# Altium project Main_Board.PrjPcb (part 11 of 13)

## Sheet eMMC.SchDoc: Pamięć nieulotna  eMMC
size A3; Organization: Altium Limited; Address1: L3, 12a Rodborough Rd; Address2: Frenchs Forest; Address3: NSW; Address4: Australia 2086
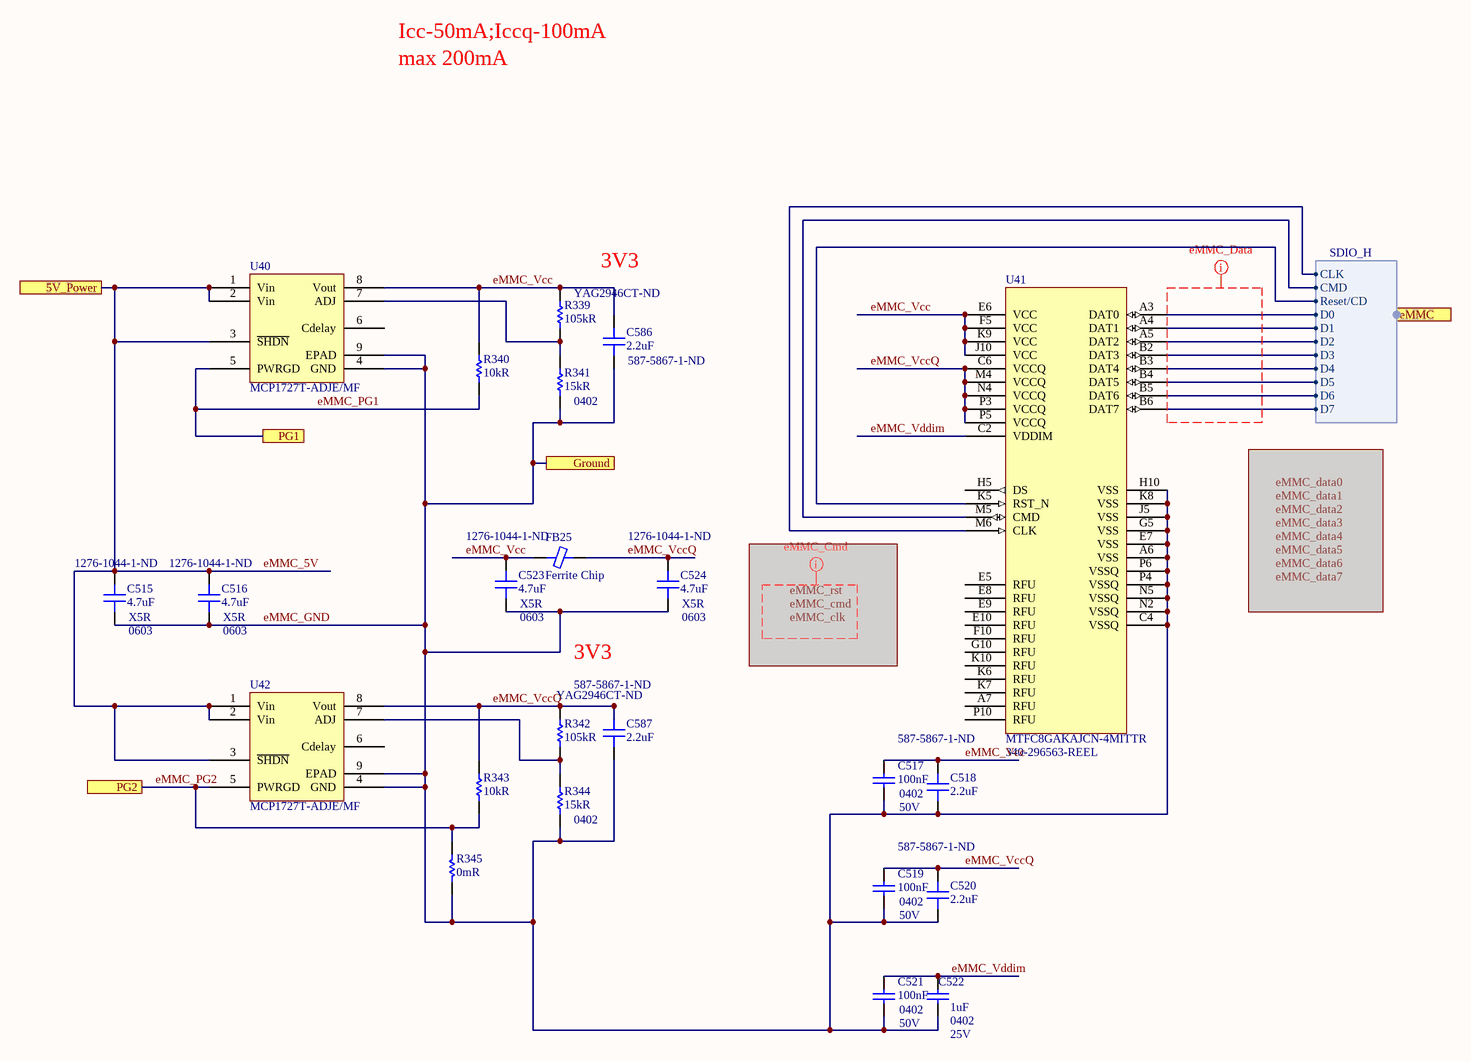
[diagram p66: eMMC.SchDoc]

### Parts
C515  4.7uF  Supplier Part Number 1: 1276-1044-1-ND  Case/Package: 0603  Dielectric: X5R  [CAP 0603/1608 RF]
C516  4.7uF  Supplier Part Number 1: 1276-1044-1-ND  Case/Package: 0603  Dielectric: X5R  [CAP 0603/1608 RF]
C517  100nF  Case Code (Imperial): 0402  Voltage: 50V  [CAP 0402/1005 KK]
C518  2.2uF  Supplier Part Number 1: 587-5867-1-ND  [CAP 0402/1005 KK]
C519  100nF  Case Code (Imperial): 0402  Voltage: 50V  [CAP 0402/1005 KK]
C520  2.2uF  Supplier Part Number 1: 587-5867-1-ND  [CAP 0402/1005 KK]
C521  100nF  Case Code (Imperial): 0402  Voltage: 50V  [CAP 0402/1005 KK]
C522  1uF  Case/Package: 0402  Voltage Rating: 25V  [CAP 0402/1005 KK]
C523  4.7uF  Supplier Part Number 1: 1276-1044-1-ND  Case/Package: 0603  Dielectric: X5R  [CAP 0603/1608 RF]
C524  4.7uF  Supplier Part Number 1: 1276-1044-1-ND  Case/Package: 0603  Dielectric: X5R  [CAP 0603/1608 RF]
C586  2.2uF  Supplier Part Number 1: 587-5867-1-ND  [CAP 0402/1005 KK]
C587  2.2uF  Supplier Part Number 1: 587-5867-1-ND  [CAP 0402/1005 KK]
FB25  Ferrite Chip  [FER 0603/1608]
R339  105kR  Supplier Part Number 1: YAG2946CT-ND  [RES 0402/1005 RF KK]
R340  10kR  [RES 0402/1005 RF KK]
R341  15kR  Case Code (Imperial): 0402  [RES 0402/1005 RF KK]
R342  105kR  Supplier Part Number 1: YAG2946CT-ND  [RES 0402/1005 RF KK]
R343  10kR  [RES 0402/1005 RF KK]
R344  15kR  Case Code (Imperial): 0402  [RES 0402/1005 RF KK]
R345  0mR  [RES 0402/1005 RF KK]
U40  MCP1727T-ADJE/MF  [MCP1727T-ADJE/MF]
U41  MTFC8GAKAJCN-4MITTR  Supplier Part Number 1: 340-296563-REEL  [MTFC8GAKAJCN-4M IT TR]
U42  MCP1727T-ADJE/MF  [MCP1727T-ADJE/MF]

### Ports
5V_Power, eMMC (harness SDIO_H), Ground, PG1, PG2

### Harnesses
SDIO_H: CLK, CMD, Reset/CD, D0, D1, D2, D3, D4, D5, D6, D7

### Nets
eMMC_GND: C515.1 C516.1 C517.1 C518.1 C519.1 C520.1 C521.1 C522.2 C523.1 C524.1 C586.1 C587.1 R341.1 R344.1 R345.2 U40.4(GND) U40.9(EPAD) U41.A6(VSS) U41.C4(VSSQ) U41.E7(VSS) U41.G5(VSS) U41.H10(VSS) U41.J5(VSS) U41.K8(VSS) U41.N2(VSSQ) U41.N5(VSSQ) U41.P4(VSSQ) U41.P6(VSSQ) U42.4(GND) U42.9(EPAD) ; port Ground  [project net B503_Ground]
eMMC_5V: C515.2 C516.2 U40.1(Vin) U40.2(Vin) U40.3(~{SHDN}) U42.1(Vin) U42.2(Vin) U42.3(~{SHDN}) ; port 5V_Power  [project net 5V_RAIL]
eMMC_clk: U41.M6(CLK) ; port eMMC.CLK
eMMC_cmd: U41.M5(CMD) ; port eMMC.CMD
eMMC_data0: U41.A3(DAT0) ; port eMMC.D0
eMMC_data1: U41.A4(DAT1) ; port eMMC.D1
eMMC_data2: U41.A5(DAT2) ; port eMMC.D2
eMMC_data3: U41.B2(DAT3) ; port eMMC.D3
eMMC_data4: U41.B3(DAT4) ; port eMMC.D4
eMMC_data5: U41.B4(DAT5) ; port eMMC.D5
eMMC_data6: U41.B5(DAT6) ; port eMMC.D6
eMMC_data7: U41.B6(DAT7) ; port eMMC.D7
eMMC_PG1: R340.1 U40.5(PWRGD) ; port PG1
eMMC_PG2: R343.1 R345.1 U42.5(PWRGD) ; port PG2
eMMC_rst: U41.K5(RST_N) ; port eMMC.Reset/CD
eMMC_Vcc: C517.2 C518.2 C523.2 C586.2 FB25.1 R339.2 R340.2 U40.8(Vout) U41.E6(VCC) U41.F5(VCC) U41.J10(VCC) U41.K9(VCC)
eMMC_VccQ: C519.2 C520.2 C524.2 C587.2 FB25.2 R342.2 R343.2 U41.C6(VCCQ) U41.M4(VCCQ) U41.N4(VCCQ) U41.P3(VCCQ) U41.P5(VCCQ) U42.8(Vout)
eMMC_Vddim: C521.2 C522.1 U41.C2(VDDIM)
NetR339_1: R339.1 R341.2 U40.7(ADJ)
NetR342_1: R342.1 R344.2 U42.7(ADJ)

Not connected (* = marked no-connect by the designer): U40 6(Cdelay); U41 A7(RFU) E5(RFU) E8(RFU) E9(RFU) E10(RFU) F10(RFU) G10(RFU) H5(DS) K6(RFU) K7(RFU) K10(RFU) P10(RFU); U42 6(Cdelay)

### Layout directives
net class eMMC_Data: (no net found under the mark)
net class eMMC_Cmd: eMMC_clk, eMMC_cmd, eMMC_rst

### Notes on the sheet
- Icc-50mA;Iccq-100mA
- max 200mA
- 3V3

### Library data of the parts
C515 C516 C523 C524 = Capacitor: Manufacturer: Samsung; Manufacturer Part Number: CL10A475KP8NNNC; Tolerance: 10%; Voltage Rating: 10V
C517 C519 C521 = Capacitor: CAP CER 0.1UF 50V X5R 0402; Manufacturer: Murata; Manufacturer Part Number: GRM155R61H104KE14D; Dielectric Material: Ceramic; Dissipation Factor: 0.025%; Tolerance: 10%
C518 C520 C586 C587 = Capacitor: CAP CER 2.2UF 6.3V X5R 0402; Manufacturer: Taiyo Yuden; Manufacturer Part Number: JMK105BJ225KV-F; Tolerance: 10%
C522 = Capacitor: MURATA - GRT155R61E105KE01D - SMD Multilayer Ceramic Capacitor, 1 µF, 25 V, 0402 [1005 Metric], ± 10%, X5R, GRT Series - SMD Multilayer Ceramic Capacitor, 1 µF, 25 V, 0402 [1005 Metric], ± 10%, X5R, GRT Series
FB25 = Ferrite Chip: SMT Ferrite Chip; Manufacturer: TDK; Manufacturer Part Number: MPZ1608S331ATA00; Tolerance: 25%; Impedance: 330R; DC Resistance (DCR): 80mR; Max DC Current: 1.7A
R339 R342 = Resistor: Thick Film Resistors - SMD 105K OHM 1%; Manufacturer: Yageo; Manufacturer Part Number: RC0402FR-07105KL; Power Rating: 62.5mW; Voltage Rating: 50V; Max Power Dissipation: 63mW; Temperature Coefficient: 100ppm/°C
R340 R343 = Resistor: Manufacturer 1: Yageo; Manufacturer Part Number 1: RC0402FR-0710KL; Tolerance: 1%; Temperature Coefficient: 100ppm/°C; Voltage Rating: 50V; Power Rating: 62.5mW
R341 R344 = Resistor: Manufacturer: Panasonic; Manufacturer Part Number: ERJ-2RKF1502X; Tolerance: 1%; Voltage Rating: 50V; Power Rating: 100mW; Temperature Coefficient: 100ppm/°C
R345 = Resistor: Manufacturer 1: Yageo; Manufacturer Part Number 1: RC0402JR-070RL; Power Rating: 62.5mW; Tolerance: 5%; Voltage Rating: 50V; Max Power Dissipation: 63mW; Temperature Coefficient: 200ppm/°C
U40 U42 = MCP1727T-ADJE/MF: IC REG LDO ADJ 1.5A 8DFN; Manufacturer 1: Microchip; Number of Outputs: 1; Min Input Voltage: 2.3V; Max Input Voltage: 6V; Output Voltage: 5V; Dropout Voltage: 330mV; Input Bias Current: 120uA; Reference Voltage: 410mV; Polarity: Positive; Accuracy: 0.5%; Output Type: Adjustable
U41 = MTFC8GAKAJCN-4MITTR: IC FLASH 64G MMC; Manufacturer 1: Micron Technology

## Sheet GTR.SchDoc: GTR
size A3; Organization: Altium Limited; Address1: L3, 12a Rodborough Rd; Address2: Frenchs Forest; Address3: NSW; Address4: Australia 2086
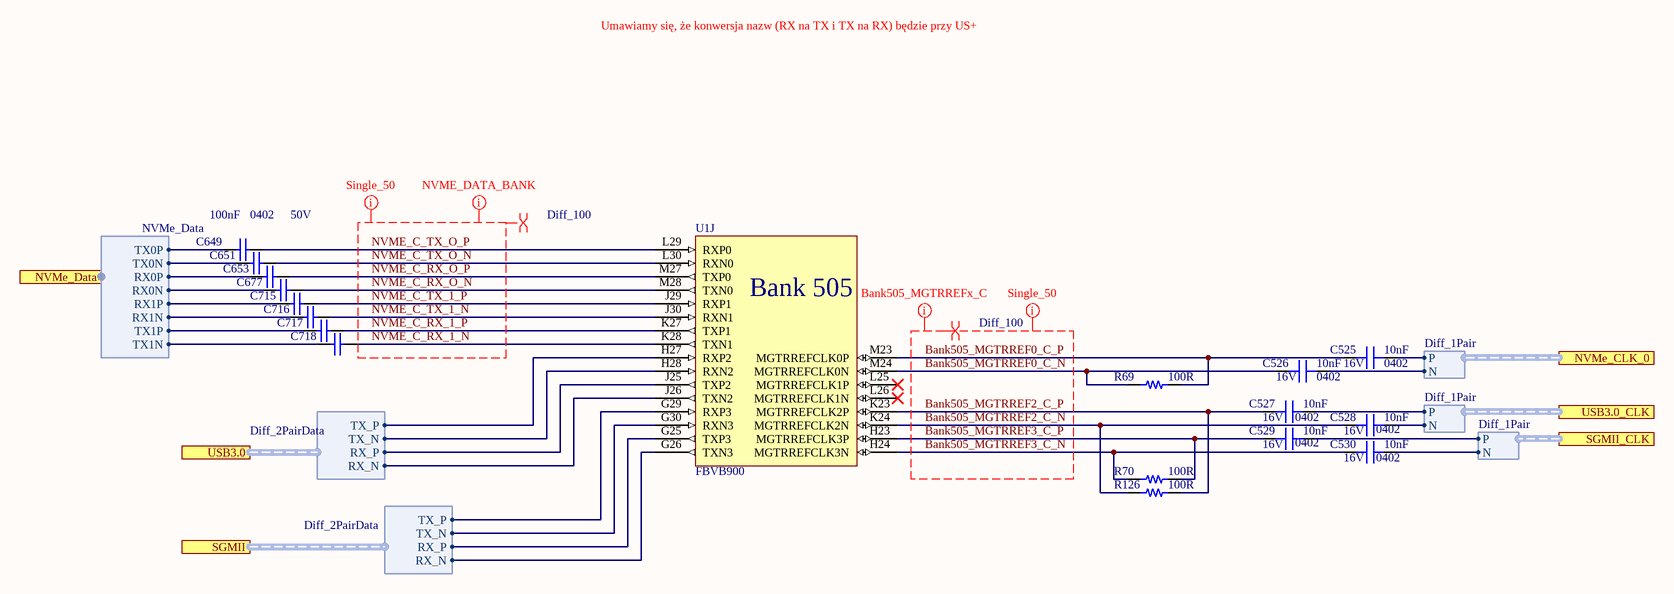
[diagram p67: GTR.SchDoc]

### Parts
C525  10nF  Case/Package: 0402  Voltage Rating (DC): 16V  [CAP 0402/1005 KK]
C526  10nF  Case/Package: 0402  Voltage Rating (DC): 16V  [CAP 0402/1005 KK]
C527  10nF  Case/Package: 0402  Voltage Rating (DC): 16V  [CAP 0402/1005 KK]
C528  10nF  Case/Package: 0402  Voltage Rating (DC): 16V  [CAP 0402/1005 KK]
C529  10nF  Case/Package: 0402  Voltage Rating (DC): 16V  [CAP 0402/1005 KK]
C530  10nF  Case/Package: 0402  Voltage Rating (DC): 16V  [CAP 0402/1005 KK]
C649  100nF  Case Code (Imperial): 0402  Voltage: 50V  [CAP 0402/1005 KK]
C651  100nF  [CAP 0402/1005 KK]  (value not drawn)
C653  100nF  [CAP 0402/1005 KK]  (value not drawn)
C677  100nF  [CAP 0402/1005 KK]  (value not drawn)
C715  100nF  [CAP 0402/1005 KK]  (value not drawn)
C716  100nF  [CAP 0402/1005 KK]  (value not drawn)
C717  100nF  [CAP 0402/1005 KK]  (value not drawn)
C718  100nF  [CAP 0402/1005 KK]  (value not drawn)
R69  100R  [RES 0402/1005 RF KK]
R70  100R  [RES 0402/1005 RF KK]
R126  100R  [RES 0402/1005 RF KK]
U1  FBVB900  [FBVB900 XX]  (part J of 23)

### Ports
NVMe_CLK_0 (harness Diff_1Pair), NVMe_Data (harness NVMe_Data), SGMII (harness Diff_2PairData), SGMII_CLK (harness Diff_1Pair), USB3.0 (harness Diff_2PairData), USB3.0_CLK (harness Diff_1Pair)

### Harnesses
NVMe_Data: RX0P, RX0N, TX0P, TX0N, RX1P, RX1N, TX1P, TX1N
Diff_1Pair: P, N
Diff_2PairData: RX_P, RX_N, TX_P, TX_N

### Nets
Bank505_MGTRREF0_C_N: C526.1 R69.2 U1.M24(MGTRREFCLK0N)
Bank505_MGTRREF0_C_P: C525.1 R69.1 U1.M23(MGTRREFCLK0P)
Bank505_MGTRREF2_C_N: C528.1 R126.2 U1.K24(MGTRREFCLK2N)
Bank505_MGTRREF2_C_P: C527.1 R126.1 U1.K23(MGTRREFCLK2P)
Bank505_MGTRREF3_C_N: C530.1 R70.2 U1.H24(MGTRREFCLK3N)
Bank505_MGTRREF3_C_P: C529.1 R70.1 U1.H23(MGTRREFCLK3P)
LTC6952_0_MATCH_Out7_N: C526.2 ; port NVMe_CLK_0.N
LTC6952_0_MATCH_Out7_P: C525.2 ; port NVMe_CLK_0.P
LTC6952_0_MATCH_Out8_N: C528.2 ; port USB3.0_CLK.N
LTC6952_0_MATCH_Out8_P: C527.2 ; port USB3.0_CLK.P
LTC6952_0_MATCH_Out9_N: C530.2 ; port SGMII_CLK.N
LTC6952_0_MATCH_Out9_P: C529.2 ; port SGMII_CLK.P
NVME_C_RX_1_N: C718.1 U1.K28(TXN1)
NVME_C_RX_1_P: C717.1 U1.K27(TXP1)
NVME_C_RX_O_N: C677.1 U1.M28(TXN0)
NVME_C_RX_O_P: C653.1 U1.M27(TXP0)
NVME_C_TX_1_N: C716.1 U1.J30(RXN1)
NVME_C_TX_1_P: C715.1 U1.J29(RXP1)
NVME_C_TX_O_N: C651.1 U1.L30(RXN0)
NVME_C_TX_O_P: C649.1 U1.L29(RXP0)
NVMe_Rx_0_N: C677.2 ; port NVMe_Data.RX0N
NVMe_Rx_0_P: C653.2 ; port NVMe_Data.RX0P
NVMe_Rx_1_N: C716.2 ; port NVMe_Data.RX1N
NVMe_Rx_1_P: C715.2 ; port NVMe_Data.RX1P
NVMe_Tx_0_N: C651.2 ; port NVMe_Data.TX0N
NVMe_Tx_0_P: C649.2 ; port NVMe_Data.TX0P
NVMe_Tx_1_N: C718.2 ; port NVMe_Data.TX1N
NVMe_Tx_1_P: C717.2 ; port NVMe_Data.TX1P
SGMI_C_Rx_N: U1.G26(TXN3) ; port SGMII.RX_N
SGMI_C_Rx_P: U1.G25(TXP3) ; port SGMII.RX_P
SGMI_C_Tx_N: U1.G29(RXP3) ; port SGMII.TX_P
SGMI_C_Tx_P: U1.G30(RXN3) ; port SGMII.TX_N
USB_RX_N: U1.J25(TXP2) ; port USB3.0.RX_P
USB_RX_P: U1.J26(TXN2) ; port USB3.0.RX_N
USB_TX_N: U1.H28(RXN2) ; port USB3.0.TX_N
USB_TX_P: U1.H27(RXP2) ; port USB3.0.TX_P

Not connected (* = marked no-connect by the designer): U1 L25(MGTRREFCLK1P)* L26(MGTRREFCLK1N)*

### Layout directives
net class Bank505_MGTRREFx_C: Bank505_MGTRREF0_C_N, Bank505_MGTRREF0_C_P, Bank505_MGTRREF2_C_N, Bank505_MGTRREF2_C_P, Bank505_MGTRREF3_C_N, Bank505_MGTRREF3_C_P
net class NVME_DATA_BANK: NVME_C_RX_1_N, NVME_C_RX_1_P, NVME_C_RX_O_N, NVME_C_RX_O_P, NVME_C_TX_1_N, NVME_C_TX_1_P, NVME_C_TX_O_N, NVME_C_TX_O_P
net class Single_50: Bank505_MGTRREF0_C_N, Bank505_MGTRREF0_C_P, Bank505_MGTRREF2_C_N, Bank505_MGTRREF2_C_P, Bank505_MGTRREF3_C_N, Bank505_MGTRREF3_C_P, NVME_C_RX_1_N, NVME_C_RX_1_P, NVME_C_RX_O_N, NVME_C_RX_O_P, NVME_C_TX_1_N, NVME_C_TX_1_P, NVME_C_TX_O_N, NVME_C_TX_O_P
differential pair; differential pair class Diff_100: Bank505_MGTRREF0_C_N, Bank505_MGTRREF0_C_P, Bank505_MGTRREF2_C_N, Bank505_MGTRREF2_C_P, Bank505_MGTRREF3_C_N, Bank505_MGTRREF3_C_P, NVME_C_RX_1_N, NVME_C_RX_1_P, NVME_C_RX_O_N, NVME_C_RX_O_P, NVME_C_TX_1_N, NVME_C_TX_1_P, NVME_C_TX_O_N, NVME_C_TX_O_P

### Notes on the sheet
- Umawiamy się, że konwersja nazw (RX na TX i TX na RX) będzie przy US+

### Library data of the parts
C525-C530 = Capacitor: Manufacturer: KEMET; Manufacturer Part Number: C0402C103K4RACTU; Dielectric Material: Ceramic; Tolerance: 10%; Dielectric: X7R; Dissipation Factor: 3.5%
C649 C651 C653 C677 C715-C718 = Capacitor: as C517 on sheet eMMC
R69 R70 R126 = Resistor: Manufacturer: Vishay Dale; Manufacturer Part Number: CRCW0402100RFKED; Tolerance: 1%; Power Rating: 63mW; Voltage Rating: 50V; Temperature Coefficient: 100ppm/°C
U1 = FBVB900: FPGA Zynq UltraScale+ Family 192150 Cells 20nm Technology 0.85V 900-Pin FCBGA Tray; Manufacturer Part Number: XCZU4CG-1FBVB900E; Manufacturer: Xilinx; Peripherals: WDT,DMA; Interface: I2C,SPI,USB,Ethernet,MMC,SDIO,SD,UART,USART,EBI/EMI; Core Architecture: ARM; RAM Size: 256KB; Frequency: 500MHz; Number of I/Os: 204

## Sheet Expander_RESET.SchDoc
size A3
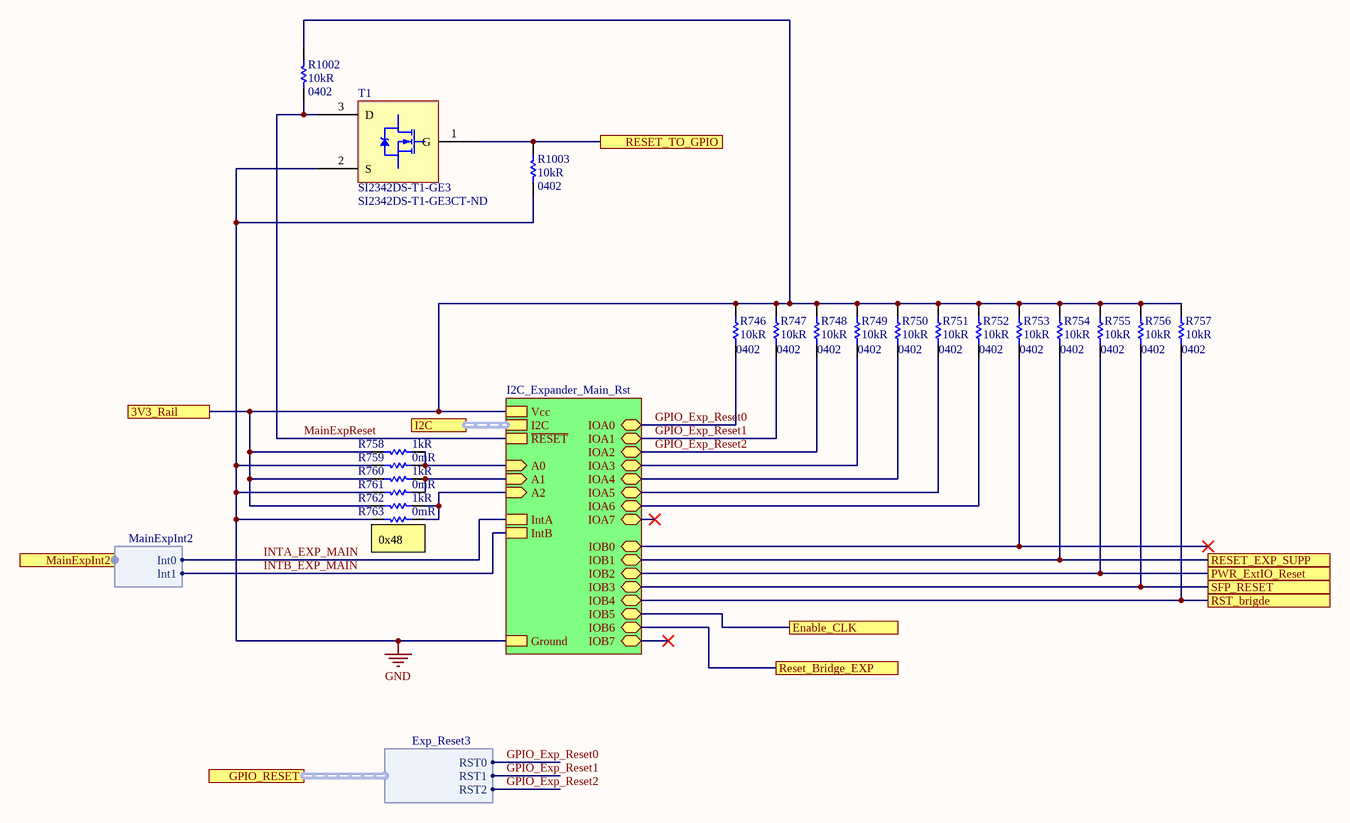
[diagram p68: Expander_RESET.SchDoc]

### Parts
R746  10kR  Case Code (Imperial): 0402  [RES 0402/1005 RF KK]
R747  10kR  Case Code (Imperial): 0402  [RES 0402/1005 RF KK]
R748  10kR  Case Code (Imperial): 0402  [RES 0402/1005 RF KK]
R749  10kR  Case Code (Imperial): 0402  [RES 0402/1005 RF KK]
R750  10kR  Case Code (Imperial): 0402  [RES 0402/1005 RF KK]
R751  10kR  Case Code (Imperial): 0402  [RES 0402/1005 RF KK]
R752  10kR  Case Code (Imperial): 0402  [RES 0402/1005 RF KK]
R753  10kR  Case Code (Imperial): 0402  [RES 0402/1005 RF KK]
R754  10kR  Case Code (Imperial): 0402  [RES 0402/1005 RF KK]
R755  10kR  Case Code (Imperial): 0402  [RES 0402/1005 RF KK]
R756  10kR  Case Code (Imperial): 0402  [RES 0402/1005 RF KK]
R757  10kR  Case Code (Imperial): 0402  [RES 0402/1005 RF KK]
R758  1kR  [RES 0402/1005 RF KK]
R759  0mR  [RES 0402/1005 RF KK]
R760  1kR  [RES 0402/1005 RF KK]
R761  0mR  [RES 0402/1005 RF KK]
R762  1kR  [RES 0402/1005 RF KK]
R763  0mR  [RES 0402/1005 RF KK]
R1002  10kR  Case Code (Imperial): 0402  [RES 0402/1005 RF KK]
R1003  10kR  Case Code (Imperial): 0402  [RES 0402/1005 RF KK]
T1  SI2342DS-T1-GE3  Supplier Part Number 1: SI2342DS-T1-GE3CT-ND  [SI2342DS-T1-GE3]

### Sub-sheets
I2C_Expander_Main_Rst = I2C_Expander.SchDoc: IOA7 (bidir), IOA3 (bidir), IOA6 (bidir), IOA1 (bidir), IOA0 (bidir), IOA5 (bidir), IOB1 (bidir), IOB2 (bidir), IOB5 (bidir), IOB6 (bidir), IOB7 (bidir), IntA, IntB, Ground, IOB4 (bidir), IOB3 (bidir), IOA2 (bidir), IOA4 (bidir), IOB0 (bidir), Vcc, ~{RESET}, I2C (harness I2C), A2 (in), A1 (in), A0 (in)

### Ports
3V3_Rail, Enable_CLK, GPIO_RESET (harness Exp_Reset3), I2C (harness I2C), MainExpInt2 (harness MainExpInt2), PWR_ExtIO_Reset, Reset_Bridge_EXP, RESET_EXP_SUPP, RESET_TO_GPIO, RST_brigde, SFP_RESET

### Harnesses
Exp_Reset3: RST0, RST1, RST2
MainExpInt2: Int0, Int1

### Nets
GND: R759.2 R761.2 R763.2 R1003.1 T1.2(S) ; sheet I2C_Expander_Main_Rst/Ground  [project net B503_Ground]
3V3_RAIL: R746.2 R747.2 R748.2 R749.2 R750.2 R751.2 R752.2 R753.2 R754.2 R755.2 R756.2 R757.2 R758.1 R760.1 R762.1 R1002.2 ; port 3V3_Rail, sheet I2C_Expander_Main_Rst/Vcc
Enable_CLK: port Enable_CLK, sheet I2C_Expander_Main_Rst/IOB5
EXPANDER_RESET: R1003.2 T1.1(G) ; port RESET_TO_GPIO
GPIO_Exp_Reset0: R746.1 ; sheet I2C_Expander_Main_Rst/IOA0, port GPIO_RESET.RST0
GPIO_Exp_Reset1: R747.1 ; sheet I2C_Expander_Main_Rst/IOA1, port GPIO_RESET.RST1
GPIO_Exp_Reset2: R748.1 ; sheet I2C_Expander_Main_Rst/IOA2, port GPIO_RESET.RST2
INTA_EXP_MAIN: sheet I2C_Expander_Main_Rst/IntA, port MainExpInt2.Int0
INTB_EXP_MAIN: sheet I2C_Expander_Main_Rst/IntB, port MainExpInt2.Int1
MainExpReset: R1002.1 T1.3(D) ; sheet I2C_Expander_Main_Rst/~{RESET}
PWR_ExtIO_nReset: R755.1 ; port PWR_ExtIO_Reset, sheet I2C_Expander_Main_Rst/IOB2
RST_brigde: R757.1 ; port RST_brigde, sheet I2C_Expander_Main_Rst/IOB4
SFP_IO_nReset: R756.1 ; port SFP_RESET, sheet I2C_Expander_Main_Rst/IOB3
NetR749_1: R749.1 ; sheet I2C_Expander_Main_Rst/IOA3
NetR750_1: R750.1 ; sheet I2C_Expander_Main_Rst/IOA4
NetR751_1: R751.1 ; sheet I2C_Expander_Main_Rst/IOA5
NetR752_1: R752.1 ; sheet I2C_Expander_Main_Rst/IOA6
NetR753_1: R753.1 ; sheet I2C_Expander_Main_Rst/IOB0
NetR754_1: R754.1 ; port RESET_EXP_SUPP, sheet I2C_Expander_Main_Rst/IOB1
NetR758_2: R758.2 R759.1 ; sheet I2C_Expander_Main_Rst/A0
NetR760_2: R760.2 R761.1 ; sheet I2C_Expander_Main_Rst/A1
NetR762_2: R762.2 R763.1 ; sheet I2C_Expander_Main_Rst/A2
NetSP12_I2C_Bridge_GPIO_1: port Reset_Bridge_EXP, sheet I2C_Expander_Main_Rst/IOB6

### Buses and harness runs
harness port I2C = sheet I2C_Expander_Main_Rst/I2C

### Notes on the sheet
- (near R763) 0x48

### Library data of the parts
R746-R757 R1002 R1003 = Resistor: Surface Mount Thick Film Resistor, Rc Series, 10 Kohm, 62.5 Mw, - 1%, 50 V, 0402 [1005 Metric]; Manufacturer: Yageo; Manufacturer Part Number: RC0402FR-0710KL; Voltage Rating: 50V; Power Rating: 62.5mW; Temperature Coefficient: 100ppm/°C
R758 R760 R762 = Resistor: PANASONIC - ERJ-2RKF1001X - SMD Chip Resistor, 0402 [1005 Metric], 1 kohm, ERJ2R Series, 50 V, Thick Film, 100 mW; Temperature Coefficient: 100ppm/°C; Tolerance: 1%; Voltage Rating (DC): 50V; Power Rating: 100mW
R759 R761 R763 = Resistor: as R345 on sheet eMMC
T1 = SI2342DS-T1-GE3: Trans MOSFET N-CH 8V 6A 3-Pin SOT-23 T/R; Manufacturer: Vishay; Rds On Max: 17mR; Input Capacitance: 1.07nF; Rise Time: 14ns; Max Power Dissipation: 2.5W; Number of Elements: 1; Power Dissipation: 1.3W; Turn-On Delay Time: 6ns; Turn-Off Delay Time: 65ns; Fall Time: 25ns; Threshold Voltage: 800mV; Gate to Source Voltage (Vgs): 5V

## Sheet US_Interrupts.SchDoc
size A3
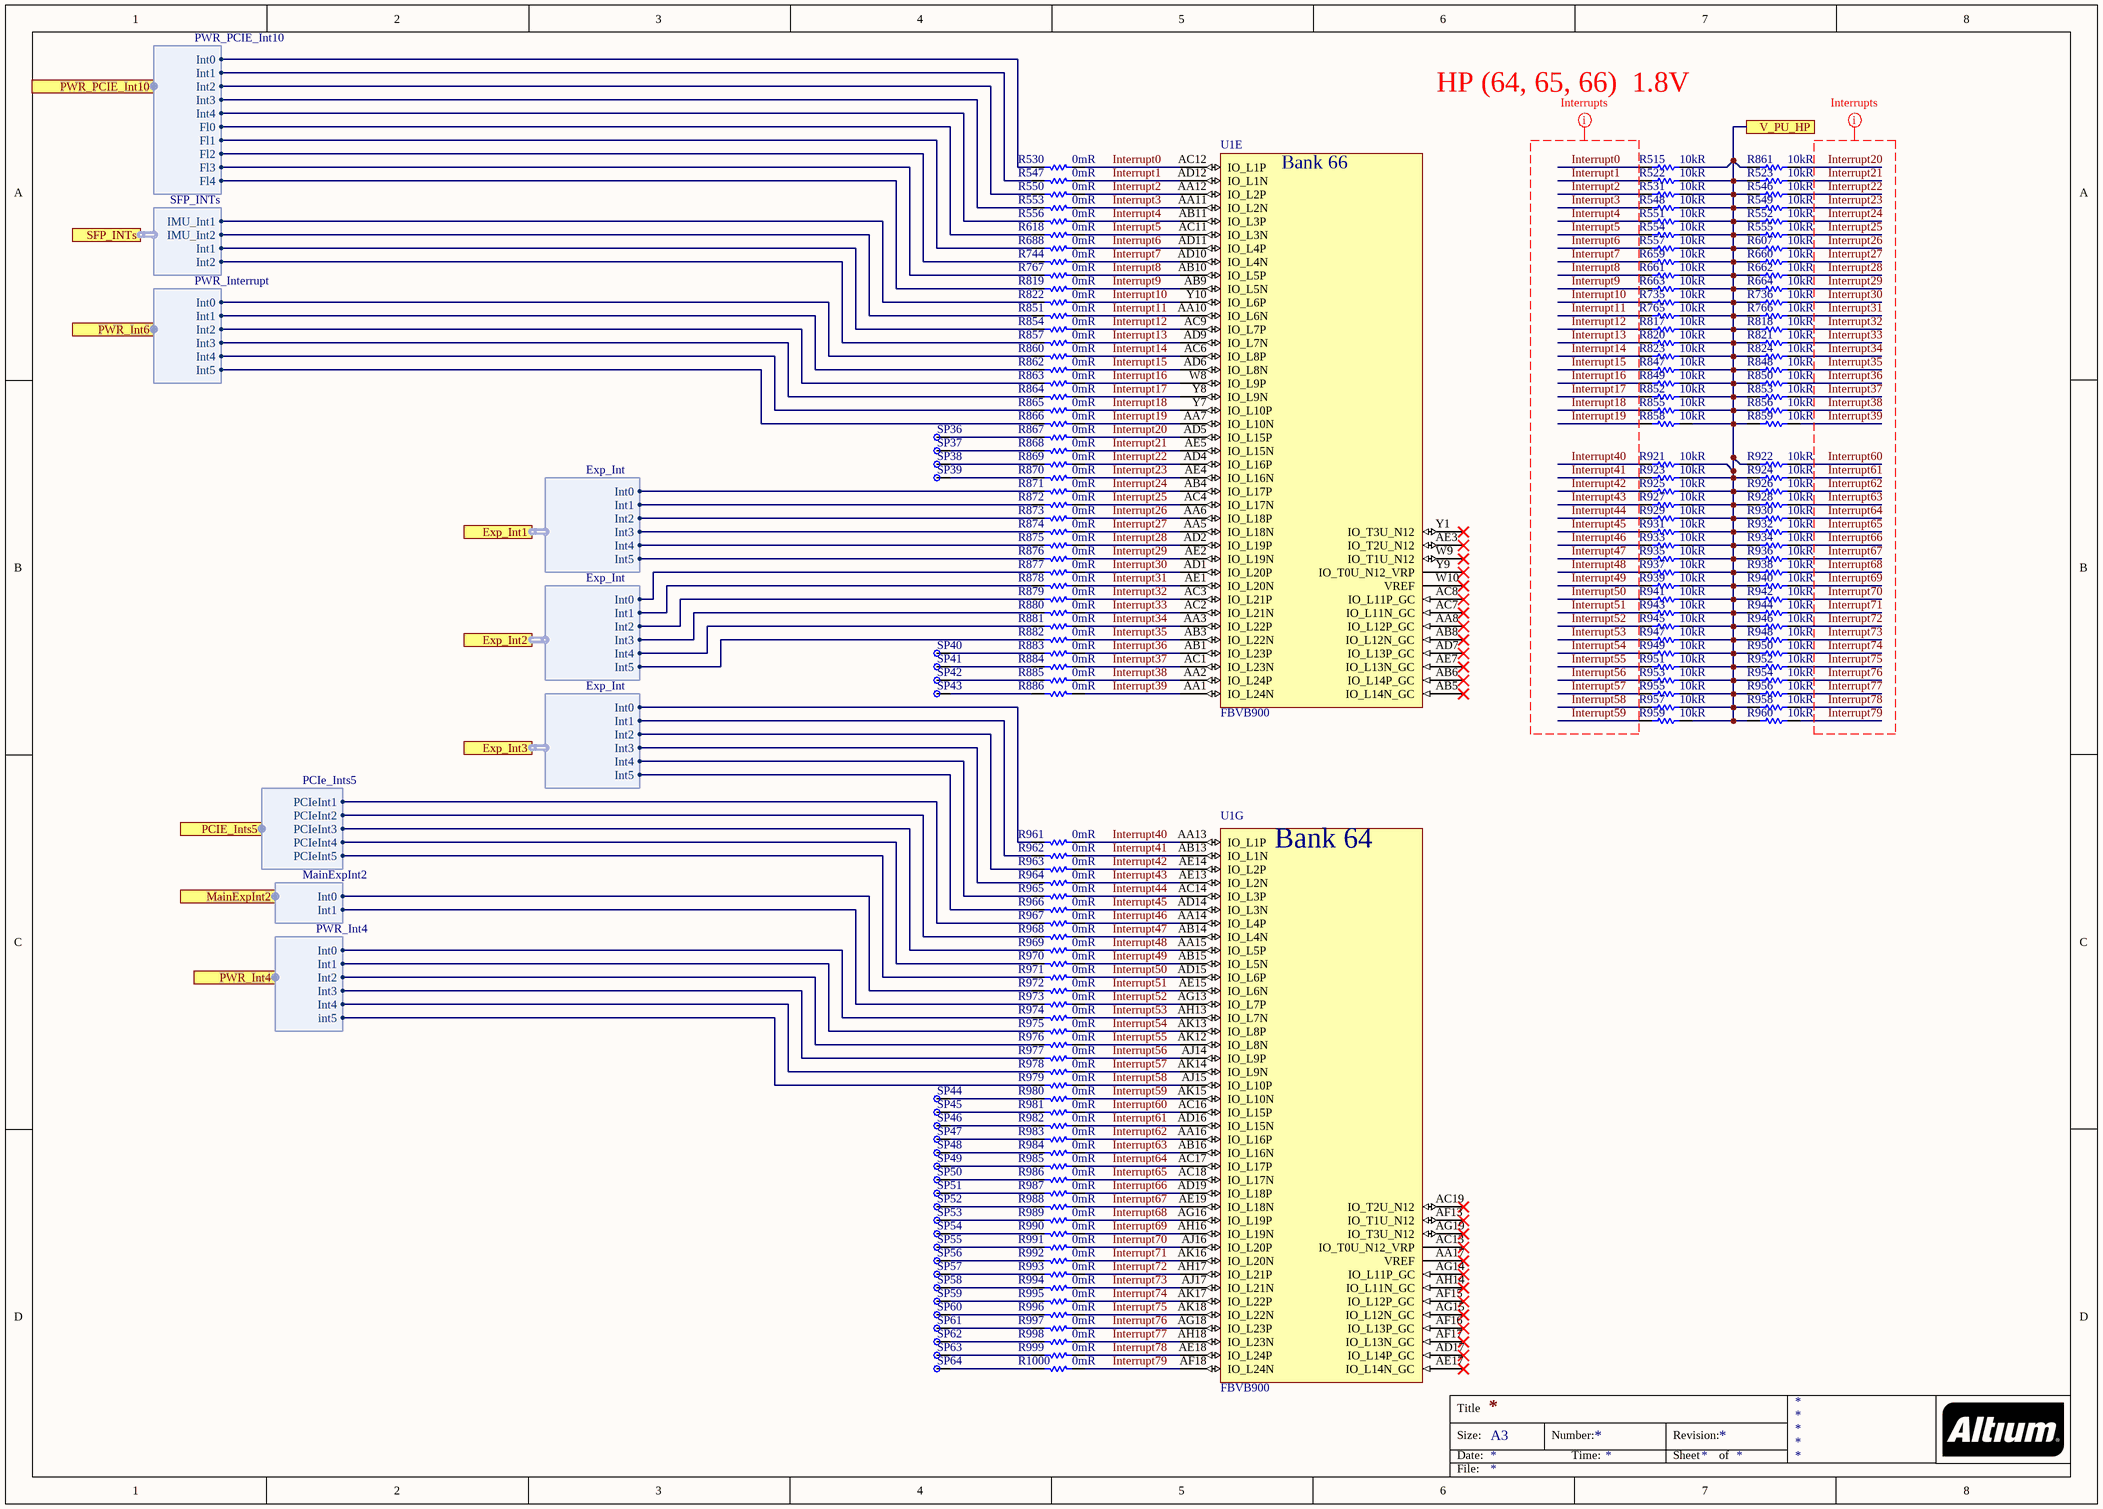
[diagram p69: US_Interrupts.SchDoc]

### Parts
R515  10kR  [RES 0402/1005 RF KK]
R522  10kR  [RES 0402/1005 RF KK]
R523  10kR  [RES 0402/1005 RF KK]
R530  0mR  [RES 0402/1005 RF KK]
R531  10kR  [RES 0402/1005 RF KK]
R546  10kR  [RES 0402/1005 RF KK]
R547  0mR  [RES 0402/1005 RF KK]
R548  10kR  [RES 0402/1005 RF KK]
R549  10kR  [RES 0402/1005 RF KK]
R550  0mR  [RES 0402/1005 RF KK]
R551  10kR  [RES 0402/1005 RF KK]
R552  10kR  [RES 0402/1005 RF KK]
R553  0mR  [RES 0402/1005 RF KK]
R554  10kR  [RES 0402/1005 RF KK]
R555  10kR  [RES 0402/1005 RF KK]
R556  0mR  [RES 0402/1005 RF KK]
R557  10kR  [RES 0402/1005 RF KK]
R607  10kR  [RES 0402/1005 RF KK]
R618  0mR  [RES 0402/1005 RF KK]
R659  10kR  [RES 0402/1005 RF KK]
R660  10kR  [RES 0402/1005 RF KK]
R661  10kR  [RES 0402/1005 RF KK]
R662  10kR  [RES 0402/1005 RF KK]
R663  10kR  [RES 0402/1005 RF KK]
R664  10kR  [RES 0402/1005 RF KK]
R688  0mR  [RES 0402/1005 RF KK]
R735  10kR  [RES 0402/1005 RF KK]
R736  10kR  [RES 0402/1005 RF KK]
R744  0mR  [RES 0402/1005 RF KK]
R765  10kR  [RES 0402/1005 RF KK]
R766  10kR  [RES 0402/1005 RF KK]
R767  0mR  [RES 0402/1005 RF KK]
R817  10kR  [RES 0402/1005 RF KK]
R818  10kR  [RES 0402/1005 RF KK]
R819  0mR  [RES 0402/1005 RF KK]
R820  10kR  [RES 0402/1005 RF KK]
R821  10kR  [RES 0402/1005 RF KK]
R822  0mR  [RES 0402/1005 RF KK]
R823  10kR  [RES 0402/1005 RF KK]
R824  10kR  [RES 0402/1005 RF KK]
R847  10kR  [RES 0402/1005 RF KK]
R848  10kR  [RES 0402/1005 RF KK]
R849  10kR  [RES 0402/1005 RF KK]
R850  10kR  [RES 0402/1005 RF KK]
R851  0mR  [RES 0402/1005 RF KK]
R852  10kR  [RES 0402/1005 RF KK]
R853  10kR  [RES 0402/1005 RF KK]
R854  0mR  [RES 0402/1005 RF KK]
R855  10kR  [RES 0402/1005 RF KK]
R856  10kR  [RES 0402/1005 RF KK]
R857  0mR  [RES 0402/1005 RF KK]
R858  10kR  [RES 0402/1005 RF KK]
R859  10kR  [RES 0402/1005 RF KK]
R860  0mR  [RES 0402/1005 RF KK]
R861  10kR  [RES 0402/1005 RF KK]
R862  0mR  [RES 0402/1005 RF KK]
R863  0mR  [RES 0402/1005 RF KK]
R864  0mR  [RES 0402/1005 RF KK]
R865  0mR  [RES 0402/1005 RF KK]
R866  0mR  [RES 0402/1005 RF KK]
R867  0mR  [RES 0402/1005 RF KK]
R868  0mR  [RES 0402/1005 RF KK]
R869  0mR  [RES 0402/1005 RF KK]
R870  0mR  [RES 0402/1005 RF KK]
R871  0mR  [RES 0402/1005 RF KK]
R872  0mR  [RES 0402/1005 RF KK]
R873  0mR  [RES 0402/1005 RF KK]
R874  0mR  [RES 0402/1005 RF KK]
R875  0mR  [RES 0402/1005 RF KK]
R876  0mR  [RES 0402/1005 RF KK]
R877  0mR  [RES 0402/1005 RF KK]
R878  0mR  [RES 0402/1005 RF KK]
R879  0mR  [RES 0402/1005 RF KK]
R880  0mR  [RES 0402/1005 RF KK]
R881  0mR  [RES 0402/1005 RF KK]
R882  0mR  [RES 0402/1005 RF KK]
R883  0mR  [RES 0402/1005 RF KK]
R884  0mR  [RES 0402/1005 RF KK]
R885  0mR  [RES 0402/1005 RF KK]
R886  0mR  [RES 0402/1005 RF KK]
R921  10kR  [RES 0402/1005 RF KK]
R922  10kR  [RES 0402/1005 RF KK]
R923  10kR  [RES 0402/1005 RF KK]
R924  10kR  [RES 0402/1005 RF KK]
R925  10kR  [RES 0402/1005 RF KK]
R926  10kR  [RES 0402/1005 RF KK]
R927  10kR  [RES 0402/1005 RF KK]
R928  10kR  [RES 0402/1005 RF KK]
R929  10kR  [RES 0402/1005 RF KK]
R930  10kR  [RES 0402/1005 RF KK]
R931  10kR  [RES 0402/1005 RF KK]
R932  10kR  [RES 0402/1005 RF KK]
R933  10kR  [RES 0402/1005 RF KK]
R934  10kR  [RES 0402/1005 RF KK]
R935  10kR  [RES 0402/1005 RF KK]
R936  10kR  [RES 0402/1005 RF KK]
R937  10kR  [RES 0402/1005 RF KK]
R938  10kR  [RES 0402/1005 RF KK]
R939  10kR  [RES 0402/1005 RF KK]
R940  10kR  [RES 0402/1005 RF KK]
R941  10kR  [RES 0402/1005 RF KK]
R942  10kR  [RES 0402/1005 RF KK]
R943  10kR  [RES 0402/1005 RF KK]
R944  10kR  [RES 0402/1005 RF KK]
R945  10kR  [RES 0402/1005 RF KK]
R946  10kR  [RES 0402/1005 RF KK]
R947  10kR  [RES 0402/1005 RF KK]
R948  10kR  [RES 0402/1005 RF KK]
R949  10kR  [RES 0402/1005 RF KK]
R950  10kR  [RES 0402/1005 RF KK]
R951  10kR  [RES 0402/1005 RF KK]
R952  10kR  [RES 0402/1005 RF KK]
R953  10kR  [RES 0402/1005 RF KK]
R954  10kR  [RES 0402/1005 RF KK]
R955  10kR  [RES 0402/1005 RF KK]
R956  10kR  [RES 0402/1005 RF KK]
R957  10kR  [RES 0402/1005 RF KK]
R958  10kR  [RES 0402/1005 RF KK]
R959  10kR  [RES 0402/1005 RF KK]
R960  10kR  [RES 0402/1005 RF KK]
R961  0mR  [RES 0402/1005 RF KK]
R962  0mR  [RES 0402/1005 RF KK]
R963  0mR  [RES 0402/1005 RF KK]
R964  0mR  [RES 0402/1005 RF KK]
R965  0mR  [RES 0402/1005 RF KK]
R966  0mR  [RES 0402/1005 RF KK]
R967  0mR  [RES 0402/1005 RF KK]
R968  0mR  [RES 0402/1005 RF KK]
R969  0mR  [RES 0402/1005 RF KK]
R970  0mR  [RES 0402/1005 RF KK]
R971  0mR  [RES 0402/1005 RF KK]
R972  0mR  [RES 0402/1005 RF KK]
R973  0mR  [RES 0402/1005 RF KK]
R974  0mR  [RES 0402/1005 RF KK]
R975  0mR  [RES 0402/1005 RF KK]
R976  0mR  [RES 0402/1005 RF KK]
R977  0mR  [RES 0402/1005 RF KK]
R978  0mR  [RES 0402/1005 RF KK]
R979  0mR  [RES 0402/1005 RF KK]
R980  0mR  [RES 0402/1005 RF KK]
R981  0mR  [RES 0402/1005 RF KK]
R982  0mR  [RES 0402/1005 RF KK]
R983  0mR  [RES 0402/1005 RF KK]
R984  0mR  [RES 0402/1005 RF KK]
R985  0mR  [RES 0402/1005 RF KK]
R986  0mR  [RES 0402/1005 RF KK]
R987  0mR  [RES 0402/1005 RF KK]
R988  0mR  [RES 0402/1005 RF KK]
R989  0mR  [RES 0402/1005 RF KK]
R990  0mR  [RES 0402/1005 RF KK]
R991  0mR  [RES 0402/1005 RF KK]
R992  0mR  [RES 0402/1005 RF KK]
R993  0mR  [RES 0402/1005 RF KK]
R994  0mR  [RES 0402/1005 RF KK]
R995  0mR  [RES 0402/1005 RF KK]
R996  0mR  [RES 0402/1005 RF KK]
R997  0mR  [RES 0402/1005 RF KK]
R998  0mR  [RES 0402/1005 RF KK]
R999  0mR  [RES 0402/1005 RF KK]
R1000  0mR  [RES 0402/1005 RF KK]
SP36  SP  [MeasureTP]  (value not drawn)
SP37  SP  [MeasureTP]  (value not drawn)
SP38  SP  [MeasureTP]  (value not drawn)
SP39  SP  [MeasureTP]  (value not drawn)
SP40  SP  [MeasureTP]  (value not drawn)
SP41  SP  [MeasureTP]  (value not drawn)
SP42  SP  [MeasureTP]  (value not drawn)
SP43  SP  [MeasureTP]  (value not drawn)
SP44  SP  [MeasureTP]  (value not drawn)
SP45  SP  [MeasureTP]  (value not drawn)
SP46  SP  [MeasureTP]  (value not drawn)
SP47  SP  [MeasureTP]  (value not drawn)
SP48  SP  [MeasureTP]  (value not drawn)
SP49  SP  [MeasureTP]  (value not drawn)
SP50  SP  [MeasureTP]  (value not drawn)
SP51  SP  [MeasureTP]  (value not drawn)
SP52  SP  [MeasureTP]  (value not drawn)
SP53  SP  [MeasureTP]  (value not drawn)
SP54  SP  [MeasureTP]  (value not drawn)
SP55  SP  [MeasureTP]  (value not drawn)
SP56  SP  [MeasureTP]  (value not drawn)
SP57  SP  [MeasureTP]  (value not drawn)
SP58  SP  [MeasureTP]  (value not drawn)
SP59  SP  [MeasureTP]  (value not drawn)
SP60  SP  [MeasureTP]  (value not drawn)
SP61  SP  [MeasureTP]  (value not drawn)
SP62  SP  [MeasureTP]  (value not drawn)
SP63  SP  [MeasureTP]  (value not drawn)
SP64  SP  [MeasureTP]  (value not drawn)
U1  FBVB900  [FBVB900 XX]  (parts E,G of 23)

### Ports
Exp_Int1 (harness Exp_Int), Exp_Int2 (harness Exp_Int), Exp_Int3 (harness Exp_Int), MainExpInt2 (harness MainExpInt2), PCIE_Ints5 (harness PCIe_Ints5), PWR_Int4 (harness PWR_Int4), PWR_Int6 (harness PWR_Interrupt), PWR_PCIE_Int10 (harness PWR_PCIE_Int10), SFP_INTs (harness SFP_INTs), V_PU_HP

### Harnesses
PWR_Interrupt: Int0, Int1, Int2, Int3, Int4, Int5
Exp_Int: Int0, Int1, Int2, Int3, Int4, Int5
PCIe_Ints5: PCIeInt1, PCIeInt2, PCIeInt3, PCIeInt4, PCIeInt5
MainExpInt2: Int0, Int1
PWR_PCIE_Int10: Int0, Int1, Int2, Int3, Int4, Fl0, Fl1, Fl2, Fl3, Fl4
SFP_INTs: IMU_Int1, Int1, Int2, IMU_Int2
PWR_Int4: Int0, Int1, Int2, Int3, Int4, int5

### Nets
Flag_PWRSwitch_PCIE0: R618.2 ; port PWR_PCIE_Int10.Fl0
Flag_PWRSwitch_PCIE1: R688.2 ; port PWR_PCIE_Int10.Fl1
Flag_PWRSwitch_PCIE2: R744.2 ; port PWR_PCIE_Int10.Fl2
Flag_PWRSwitch_PCIE3: R767.2 ; port PWR_PCIE_Int10.Fl3
Flag_PWRSwitch_PCIE4: R819.2 ; port PWR_PCIE_Int10.Fl4
GPIO_Exp10_Int0: R871.2 ; port Exp_Int1.Int0
GPIO_Exp10_Int1: R872.2 ; port Exp_Int1.Int1
GPIO_Exp11_Int0: R873.2 ; port Exp_Int1.Int2
GPIO_Exp11_Int1: R874.2 ; port Exp_Int1.Int3
GPIO_Exp12_Int0: R875.2 ; port Exp_Int1.Int4
GPIO_Exp12_Int1: R876.2 ; port Exp_Int1.Int5
GPIO_Exp13_Int0: R877.2 ; port Exp_Int2.Int0
GPIO_Exp13_Int1: R878.2 ; port Exp_Int2.Int1
GPIO_Exp14_Int0: R879.2 ; port Exp_Int2.Int2
GPIO_Exp14_Int1: R880.2 ; port Exp_Int2.Int3
GPIO_Exp15_Int0: R881.2 ; port Exp_Int2.Int4
GPIO_Exp15_Int1: R882.2 ; port Exp_Int2.Int5
IMU_INT1: R822.2 ; port SFP_INTs.IMU_Int1
IMU_INT2: R851.2 ; port SFP_INTs.IMU_Int2
INTA_EXP_MAIN: R972.2 ; port MainExpInt2.Int0
INTB_EXP_MAIN: R973.2 ; port MainExpInt2.Int1
Interrupt0: R515.2 R530.1 U1.AC12(IO_L1P)
Interrupt1: R522.2 R547.1 U1.AD12(IO_L1N)
Interrupt2: R531.2 R550.1 U1.AA12(IO_L2P)
Interrupt3: R548.2 R553.1 U1.AA11(IO_L2N)
Interrupt4: R551.2 R556.1 U1.AB11(IO_L3P)
Interrupt5: R554.2 R618.1 U1.AC11(IO_L3N)
Interrupt6: R557.2 R688.1 U1.AD11(IO_L4P)
Interrupt7: R659.2 R744.1 U1.AD10(IO_L4N)
Interrupt8: R661.2 R767.1 U1.AB10(IO_L5P)
Interrupt9: R663.2 R819.1 U1.AB9(IO_L5N)
Interrupt10: R735.2 R822.1 U1.Y10(IO_L6P)
Interrupt11: R765.2 R851.1 U1.AA10(IO_L6N)
Interrupt12: R817.2 R854.1 U1.AC9(IO_L7P)
Interrupt13: R820.2 R857.1 U1.AD9(IO_L7N)
Interrupt14: R823.2 R860.1 U1.AC6(IO_L8P)
Interrupt15: R847.2 R862.1 U1.AD6(IO_L8N)
Interrupt16: R849.2 R863.1 U1.W8(IO_L9P)
Interrupt17: R852.2 R864.1 U1.Y8(IO_L9N)
Interrupt18: R855.2 R865.1 U1.Y7(IO_L10P)
Interrupt19: R858.2 R866.1 U1.AA7(IO_L10N)
Interrupt20: R861.1 R867.1 U1.AD5(IO_L15P)
Interrupt21: R523.1 R868.1 U1.AE5(IO_L15N)
Interrupt22: R546.1 R869.1 U1.AD4(IO_L16P)
Interrupt23: R549.1 R870.1 U1.AE4(IO_L16N)
Interrupt24: R552.1 R871.1 U1.AB4(IO_L17P)
Interrupt25: R555.1 R872.1 U1.AC4(IO_L17N)
Interrupt26: R607.1 R873.1 U1.AA6(IO_L18P)
Interrupt27: R660.1 R874.1 U1.AA5(IO_L18N)
Interrupt28: R662.1 R875.1 U1.AD2(IO_L19P)
Interrupt29: R664.1 R876.1 U1.AE2(IO_L19N)
Interrupt30: R736.1 R877.1 U1.AD1(IO_L20P)
Interrupt31: R766.1 R878.1 U1.AE1(IO_L20N)
Interrupt32: R818.1 R879.1 U1.AC3(IO_L21P)
Interrupt33: R821.1 R880.1 U1.AC2(IO_L21N)
Interrupt34: R824.1 R881.1 U1.AA3(IO_L22P)
Interrupt35: R848.1 R882.1 U1.AB3(IO_L22N)
Interrupt36: R850.1 R883.1 U1.AB1(IO_L23P)
Interrupt37: R853.1 R884.1 U1.AC1(IO_L23N)
Interrupt38: R856.1 R885.1 U1.AA2(IO_L24P)
Interrupt39: R859.1 R886.1 U1.AA1(IO_L24N)
Interrupt40: R921.2 R961.1 U1.AA13(IO_L1P)
Interrupt41: R923.2 R962.1 U1.AB13(IO_L1N)
Interrupt42: R925.2 R963.1 U1.AE14(IO_L2P)
Interrupt43: R927.2 R964.1 U1.AE13(IO_L2N)
Interrupt44: R929.2 R965.1 U1.AC14(IO_L3P)
Interrupt45: R931.2 R966.1 U1.AD14(IO_L3N)
Interrupt46: R933.2 R967.1 U1.AA14(IO_L4P)
Interrupt47: R935.2 R968.1 U1.AB14(IO_L4N)
Interrupt48: R937.2 R969.1 U1.AA15(IO_L5P)
Interrupt49: R939.2 R970.1 U1.AB15(IO_L5N)
Interrupt50: R941.2 R971.1 U1.AD15(IO_L6P)
Interrupt51: R943.2 R972.1 U1.AE15(IO_L6N)
Interrupt52: R945.2 R973.1 U1.AG13(IO_L7P)
Interrupt53: R947.2 R974.1 U1.AH13(IO_L7N)
Interrupt54: R949.2 R975.1 U1.AK13(IO_L8P)
Interrupt55: R951.2 R976.1 U1.AK12(IO_L8N)
Interrupt56: R953.2 R977.1 U1.AJ14(IO_L9P)
Interrupt57: R955.2 R978.1 U1.AK14(IO_L9N)
Interrupt58: R957.2 R979.1 U1.AJ15(IO_L10P)
Interrupt59: R959.2 R980.1 U1.AK15(IO_L10N)
Interrupt60: R922.1 R981.1 U1.AC16(IO_L15P)
Interrupt61: R924.1 R982.1 U1.AD16(IO_L15N)
Interrupt62: R926.1 R983.1 U1.AA16(IO_L16P)
Interrupt63: R928.1 R984.1 U1.AB16(IO_L16N)
Interrupt64: R930.1 R985.1 U1.AC17(IO_L17P)
Interrupt65: R932.1 R986.1 U1.AC18(IO_L17N)
Interrupt66: R934.1 R987.1 U1.AD19(IO_L18P)
Interrupt67: R936.1 R988.1 U1.AE19(IO_L18N)
Interrupt68: R938.1 R989.1 U1.AG16(IO_L19P)
Interrupt69: R940.1 R990.1 U1.AH16(IO_L19N)
Interrupt70: R942.1 R991.1 U1.AJ16(IO_L20P)
Interrupt71: R944.1 R992.1 U1.AK16(IO_L20N)
Interrupt72: R946.1 R993.1 U1.AH17(IO_L21P)
Interrupt73: R948.1 R994.1 U1.AJ17(IO_L21N)
Interrupt74: R950.1 R995.1 U1.AK17(IO_L22P)
Interrupt75: R952.1 R996.1 U1.AK18(IO_L22N)
Interrupt76: R954.1 R997.1 U1.AG18(IO_L23P)
Interrupt77: R956.1 R998.1 U1.AH18(IO_L23N)
Interrupt78: R958.1 R999.1 U1.AE18(IO_L24P)
Interrupt79: R960.1 R1000.1 U1.AF18(IO_L24N)
P4HS_PowerAlert_Pcie0: R530.2 ; port PWR_PCIE_Int10.Int0
P4HS_PowerAlert_Pcie1: R547.2 ; port PWR_PCIE_Int10.Int1
P4HS_PowerAlert_Pcie2: R550.2 ; port PWR_PCIE_Int10.Int2
P4HS_PowerAlert_Pcie3: R553.2 ; port PWR_PCIE_Int10.Int3
P4HS_PowerAlert_Pcie4: R556.2 ; port PWR_PCIE_Int10.Int4
PWR_ExtIO_INT0: R977.2 ; port PWR_Int4.Int3
PWR_ExtIO_INT1: R976.2 ; port PWR_Int4.Int2
PWR_ExtIO_INT2: R978.2 ; port PWR_Int4.Int4
PWR_ExtIO_INT3: R979.2 ; port PWR_Int4.int5
PWR_PowerAlert0: R974.2 ; port PWR_Int4.Int0
PWR_PowerAlert1: R975.2 ; port PWR_Int4.Int1
SFP_INT0: R854.2 ; port SFP_INTs.Int1
SFP_INT1: R857.2 ; port SFP_INTs.Int2
US+_MGTVccAux: R515.1 R522.1 R523.2 R531.1 R546.2 R548.1 R549.2 R551.1 R552.2 R554.1 R555.2 R557.1 R607.2 R659.1 R660.2 R661.1 R662.2 R663.1 R664.2 R735.1 R736.2 R765.1 R766.2 R817.1 R818.2 R820.1 R821.2 R823.1 R824.2 R847.1 R848.2 R849.1 R850.2 R852.1 R853.2 R855.1 R856.2 R858.1 R859.2 R861.2 R921.1 R922.2 R923.1 R924.2 R925.1 R926.2 R927.1 R928.2 R929.1 R930.2 R931.1 R932.2 R933.1 R934.2 R935.1 R936.2 R937.1 R938.2 R939.1 R940.2 R941.1 R942.2 R943.1 R944.2 R945.1 R946.2 R947.1 R948.2 R949.1 R950.2 R951.1 R952.2 R953.1 R954.2 R955.1 R956.2 R957.1 R958.2 R959.1 R960.2 ; port V_PU_HP
NetJ1_PCIE0_43: R967.2 ; port PCIE_Ints5.PCIeInt1
NetJ1_PCIE1_43: R968.2 ; port PCIE_Ints5.PCIeInt2
NetJ1_PCIE2_43: R969.2 ; port PCIE_Ints5.PCIeInt3
NetJ1_PCIE3_43: R970.2 ; port PCIE_Ints5.PCIeInt4
NetJ1_PCIE4_43: R971.2 ; port PCIE_Ints5.PCIeInt5
NetR860_2: R860.2 ; port PWR_Int6.Int0
NetR862_2: R862.2 ; port PWR_Int6.Int1
NetR863_2: R863.2 ; port PWR_Int6.Int2
NetR864_2: R864.2 ; port PWR_Int6.Int3
NetR865_2: R865.2 ; port PWR_Int6.Int4
NetR866_2: R866.2 ; port PWR_Int6.Int5
NetR867_2: R867.2 SP36.1
NetR868_2: R868.2 SP37.1
NetR869_2: R869.2 SP38.1
NetR870_2: R870.2 SP39.1
NetR883_2: R883.2 SP40.1
NetR884_2: R884.2 SP41.1
NetR885_2: R885.2 SP42.1
NetR886_2: R886.2 SP43.1
NetR961_2: R961.2 ; port Exp_Int3.Int0
NetR962_2: R962.2 ; port Exp_Int3.Int1
NetR963_2: R963.2 ; port Exp_Int3.Int2
NetR964_2: R964.2 ; port Exp_Int3.Int3
NetR965_2: R965.2 ; port Exp_Int3.Int4
NetR966_2: R966.2 ; port Exp_Int3.Int5
NetR980_2: R980.2 SP44.1
NetR981_2: R981.2 SP45.1
NetR982_2: R982.2 SP46.1
NetR983_2: R983.2 SP47.1
NetR984_2: R984.2 SP48.1
NetR985_2: R985.2 SP49.1
NetR986_2: R986.2 SP50.1
NetR987_2: R987.2 SP51.1
NetR988_2: R988.2 SP52.1
NetR989_2: R989.2 SP53.1
NetR990_2: R990.2 SP54.1
NetR991_2: R991.2 SP55.1
NetR992_2: R992.2 SP56.1
NetR993_2: R993.2 SP57.1
NetR994_2: R994.2 SP58.1
NetR995_2: R995.2 SP59.1
NetR996_2: R996.2 SP60.1
NetR997_2: R997.2 SP61.1
NetR998_2: R998.2 SP62.1
NetR999_2: R999.2 SP63.1
NetR1000_2: R1000.2 SP64.1

Not connected (* = marked no-connect by the designer): U1 AA8(IO_L12P_GC)* AA17(VREF)* AB5(IO_L14N_GC)* AB6(IO_L14P_GC)* AB8(IO_L12N_GC)* AC7(IO_L11N_GC)* AC8(IO_L11P_GC)* AC13(IO_T0U_N12_VRP)* AC19(IO_T2U_N12)* AD7(IO_L13P_GC)* AD17(IO_L14P_GC)* AE3(IO_T2U_N12)* AE7(IO_L13N_GC)* AE17(IO_L14N_GC)* AF13(IO_T1U_N12)* AF15(IO_L12P_GC)* AF16(IO_L13P_GC)* AF17(IO_L13N_GC)* AG14(IO_L11P_GC)* AG15(IO_L12N_GC)* AG19(IO_T3U_N12)* AH14(IO_L11N_GC)* W9(IO_T1U_N12)* W10(VREF)* Y1(IO_T3U_N12)* Y9(IO_T0U_N12_VRP)*

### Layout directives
net class Interrupt_Line: Interrupt0, Interrupt1, Interrupt2, Interrupt3, Interrupt4, Interrupt5, Interrupt6, Interrupt7, Interrupt8, Interrupt9, Interrupt10, Interrupt11, Interrupt12, Interrupt13, Interrupt14, Interrupt15, Interrupt16, Interrupt17, Interrupt18, Interrupt19, Interrupt20, Interrupt21, Interrupt22, Interrupt23, Interrupt24, Interrupt25, Interrupt26, Interrupt27, Interrupt28, Interrupt29, Interrupt30, Interrupt31, Interrupt32, Interrupt33, Interrupt34, Interrupt35, Interrupt36, Interrupt37, Interrupt38, Interrupt39, Interrupt40, Interrupt41, Interrupt42, Interrupt43, Interrupt44, Interrupt45, Interrupt46, Interrupt47, Interrupt48, Interrupt49, Interrupt50, Interrupt51, Interrupt52, Interrupt53, Interrupt54, Interrupt55, Interrupt56, Interrupt57, Interrupt58, Interrupt59, Interrupt60, Interrupt61, Interrupt62, Interrupt63, Interrupt64, Interrupt65, Interrupt66, Interrupt67, Interrupt68, Interrupt69, Interrupt70, Interrupt71, Interrupt72, Interrupt73, Interrupt74, Interrupt75, Interrupt76, Interrupt77, Interrupt78, Interrupt79

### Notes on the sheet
- HP (64, 65, 66)  1.8V

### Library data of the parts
R515 R522 R523 R531 R546 R548 R549 R551 R552 R554 R555 R557 R607 R659-R664 R735 R736 R765 R766 R817 R818 R820 R821 R823 R824 R847-R850 R852 R853 R855 R856 R858 R859 R861 R921-R960 = Resistor: as R340 on sheet eMMC
R530 R547 R550 R553 R556 R618 R688 R744 R767 R819 R822 R851 R854 R857 R860 R862-R886 R961-R1000 = Resistor: as R345 on sheet eMMC
U1 = FBVB900: as U1 on sheet GTR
